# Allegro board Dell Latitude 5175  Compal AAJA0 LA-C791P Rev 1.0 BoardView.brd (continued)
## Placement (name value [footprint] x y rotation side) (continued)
D41  AZ5B25-01F_DFN0603P2Y  [ESD108-B1-CSP0201_WLL-2-1-2]  15.98 22.18 90 bottom
D42  AZ5B25-01F_DFN0603P2Y  [ESD108-B1-CSP0201_WLL-2-1-2]  15.24 22.18 90 bottom
DA2  -  [ESD207-B1-02EL_TSLP-2-19-2]  6.52 143.04 180 top
DA4  -  [PJSOT24CW_SOT323-3]  22.64 127.73 90 top
DA5  -  [ESD207-B1-02EL_TSLP-2-19-2]  12.93 142.76 0 bottom
DA6  -  [ESD207-B1-02EL_TSLP-2-19-2]  11.79 142.63 270 bottom
DA7  -  [PJSOT24CW_SOT323-3]  20.01 100.39 180 bottom
DA8  -  [TVNST52302AB0_SOT523-3]  19.74 83.8 180 bottom
DA9  -  [TVNST52302AB0_SOT523-3]  8.74 141.61 180 top
DA10  -  [ESD207-B1-02EL_TSLP-2-19-2]  5.3 144.76 270 top
DA11  -  [ESD207-B1-02EL_TSLP-2-19-2]  9.9 144 0 top
DI1  -  [TVNST52302AB0_SOT523-3]  179.6 100.12 270 top
DI2  -  [TVNST52302AB0_SOT523-3]  182.97 100.12 90 top
FD1  -  [FIDUCIAL_C40M80]  200.2 151.28 0 top
FD2  -  [FIDUCIAL_C40M80]  6.06 8.54 0 top
FD3  -  [FIDUCIAL_C40M80]  21.85 151.43 180 bottom
FD4  -  [FIDUCIAL_C40M80]  221.02 95.21 180 bottom
H1  -  [H_4P6]  33.78 21.25 0 top
H2  -  [H_4P6]  184.68 90.4 0 top
H3  -  [H_2P3]  9.68 158.92 0 top
H4  -  [H_4P6]  175.58 136.6 0 top
H5  -  [H_4P6]  10.69 115.92 0 top
H6  -  [H_4P6]  69.08 150.9 0 top
H7  -  [H_4P6]  185.68 149.6 0 top
H8  -  [H_1P2]  89.01 114 0 top
H9  -  [H_1P2]  50.83 120 0 top
H10  -  [H_1P5X2P1]  29.64 13.99 0 top
H11  -  [H_2P8]  6.18 3.75 0 top
H13  -  [H_1P4X0P4N]  46.15 100.7 90 top
H14  -  [H_1P4X0P4N]  23.51 125.3 90 top
H15  -  [H_1P4X0P4N]  29.28 131.08 0 top
H16  -  [H_1P4X0P4N]  131.85 109.86 90 top
H17  -  [H_1P4X0P4N]  131.86 122.39 90 top
H18  -  [H_1P4X0P4N]  147.42 104.08 0 top
H19  -  [H_1P3X0P4N]  46.15 124.65 90 top
H20  -  [H_1P4X0P4N]  104.08 128.17 0 top
H21  -  [H_1P4X0P4N]  47.98 93.92 0 top
H22  -  [H_1P4X0P4N]  23.51 113.22 90 top
H23  -  [H_4P6]  21.23 143.17 0 top
H24  -  [H_1P8X1P5]  190.03 148.75 0 top
H25  -  [H_2P8]  9.68 44.74 0 top
H26  -  [H_1P5]  19.48 148.75 0 top
H27  -  [H_1P4X0P4N]  98.3 122.4 90 top
H28  -  [H_1P4X0P4N]  98.3 109.85 90 top
H29  -  [H_1P4X0P4N]  45.11 34.05 90 top
H30  -  [H_1P4X0P4N]  45.11 86 90 top
H31  -  [H_1P4X0P4N]  45.11 61.7 90 top
H32  -  [H_1P4X0P4N]  45.11 69.52 90 top
H33  -  [H_1P4X0P4N]  39.18 89.58 180 top
H34  -  [H_1P4X0P4N]  39.53 67.63 180 top
H35  -  [H_2P8]  9.08 23.85 0 top
JAPS2  ACES_50506-01841-P01  [ACES_50506-01841-P01_18P-NPM]  75.64 129.48 180 top
JCAM3  ACES_50463-0104A-001  [ACES_50463-0104A-001_10P]  101.94 133.18 270 bottom
JDEG1  ACES_50521-01041-P01  [ACES_50521-01041-P01_10P]  192.63 146.6 0 bottom
JDMIC1  E-T_6918K-Y04N-00L  [E-T_6918K-Y04N-00L_4P-T]  152.61 130.94 0 bottom
JEDP1  HRS_FH35C-45S-0P3SHW(50)  [HRS_FH35C-45S-0P3SHW-50_45P-T]  114.03 94.84 180 bottom
JHDMI1  SINGA_2HE2016-100211F  [SINGA_2HE2016-100211F_19P-T]  10.31 49.95 270 top
JHP1  SINGA_2SJ3095-079111F  [SINGA_2SJ3095-079111F_6P-T]  12.56 145.96 270 bottom
JIO1  HRS_DF40C-60DS-0P4V(51)  [HRS_DF40C-60DS-0P4V-51_60P-T]  220.89 120.08 90 bottom
JIO4  HRS_DF40C-100DS-0P4V(51)  [HRS_DF40C-100DS-0P4V-51_100P-T]  140.72 98.34 180 bottom
JLPDE1  ACES_50521-01041-P01  [ACES_50521-01041-P01_10P]  219.73 103.2 270 bottom
JNFC1  LCN_BAM04-20093-0500  [LCN_BAM04-20093-0500_20P]  209.01 98.56 270 bottom
JNGFF1  BELLW_80149-2021  [BELLW_80149-2021_67P]  202.96 148.21 270 bottom
JNGFF2  LCN_DAN05-67216-S503  [LCN_DAN05-67216-S503_75P-T-S]  43.03 104.77 180 bottom
JNGFF3  LCN_DAN05-67216-S500  [LCN_DAN05-67216-S500_75P-T-S]  54.76 133.89 90 bottom
JPWR2  E-T_3806K-F03N-33L  [E-T_3806K-F03N-33L_3P]  41.68 19.4 180 bottom
JRTC1  ACES_50278-00201-001  [ACES_50278-00201-001_2P]  20.18 20.7 180 bottom
JSPI1  ACES_50696-0200M-P01  [ACES_50696-0200M-P01_20P-NPM]  49.71 147.51 180 top
JSPKL  ACES_50208-00201-P03  [ACES_50208-00201-P03_2P]  20.08 80.8 180 bottom
JT100  ACES_50278-01001-001  [ACES_50278-01001-001_10P]  162.29 101.21 180 bottom
JTS1  ACES_50506-01241-P01  [ACES_50506-01241-P01_12P]  176.53 98.48 180 bottom
JUFC  ACES_50515-03941-P02  [ACES_50515-03941-P02_39P]  113.36 134.3 180 bottom
JUSB1  TAIWI_USB034-107CRL-TWD  [TAIWI_USB034-107CRL-TWD_10P-T]  11.78 37.72 90 bottom
JUSBC1  JAE_DX07S024XJ1  [JAE_DX07S024XJ1_24P-T]  8.09 18.8 270 top
JUSH1  E-T_6705K-Y26N-00L  [E-T_6705K-Y26N-00L_26P]  203.43 99.9 180 bottom
JWFC  ACES_50515-03941-P02  [ACES_50515-03941-P02_39P]  133.7 134.3 180 bottom
JXDP1  E-T_6601K-Y61N-04L  [E-T_6601K-Y61N-04L_61P]  75.84 99.12 0 bottom
L1  BLM15PX330SN1D_2P  [MURAT_BLM15PX330SN1D_2P]  8.1 144.12 90 top
L2  BLM15PX330SN1D_2P  [MURAT_BLM15PX330SN1D_2P]  10 140.57 180 top
L3  BLM15AX700SN1D_2P  [MURAT_BLM15AX100SN1D_2P]  7.41 140.93 180 top
L4  DLW21HN900HQ2L_4P  [MURAT_DLW21HN900HQ2L_4P]  53.26 133.8 0 top
L5  FBMA-L11-160808-800LMT_0603  [KC_FBMA-L11-160808-800LMT_2P]  198.03 133.95 180 top
L6  1UH_1269AS-H-1R0M-P2_2.5A_20%  [TOKO_1269AS-H-1R0M-P2_2P]  126.14 130.04 90 top
L7  DLW21HN900HQ2L_4P  [MURAT_DLW21HN900HQ2L_4P]  114.67 127.46 90 top
L8  DLW21HN900HQ2L_4P  [MURAT_DLW21HN900HQ2L_4P]  116.6 127.46 90 top
L9  DLW21HN900HQ2L_4P  [MURAT_DLW21HN900HQ2L_4P]  118.56 127.46 90 top
L10  1NH_LQG15HN1N0S02D_0.3NH  [MURAT_LQG15HN1N0S02D_2P]  72.95 123.41 270 top
L11  BLM18EG221SN1D_2P  [MURAT_BLM18EG221SN1D_2P]  54.76 111.19 90 top
L12  HCM1012GH900BP_4P  [INPAQ_HCM1012GH900BP_4P]  106.98 103.05 270 top
L13  HCM1012GH900BP_4P  [INPAQ_HCM1012GH900BP_4P]  108.38 103.05 270 top
L14  HCM1012GH900BP_4P  [INPAQ_HCM1012GH900BP_4P]  109.77 103.05 270 top
L15  2.2UH_LQM2MPN2R2NG0L_30%  [MURAT_LQM2MPN2R2NG0L_2P]  57.01 101.49 180 top
L16  BLM15AX700SN1D_2P  [MURAT_BLM15AX100SN1D_2P]  8.87 142.79 0 bottom
L17  DLW21HN900HQ2L_4P  [MURAT_DLW21HN900HQ2L_4P]  133.52 124.96 90 bottom
L18  DLW21HN900HQ2L_4P  [MURAT_DLW21HN900HQ2L_4P]  138.83 124.95 90 bottom
L19  DLW21HN900HQ2L_4P  [MURAT_DLW21HN900HQ2L_4P]  144.95 124.95 90 bottom
L20  DLW21HN900HQ2L_4P  [MURAT_DLW21HN900HQ2L_4P]  142.93 124.95 90 bottom
L21  DLW21HN900HQ2L_4P  [MURAT_DLW21HN900HQ2L_4P]  140.77 124.95 90 bottom
L22  DLW21HN900HQ2L_4P  [MURAT_DLW21HN900HQ2L_4P]  209.19 119.4 0 bottom
L23  DLW21HN900HQ2L_4P  [MURAT_DLW21HN900HQ2L_4P]  30.42 111.02 270 bottom
L24  BLM18EG221SN1D_2P  [MURAT_BLM18EG221SN1D_2P]  55.28 122.42 0 top
L25  BLM15HD601SN1D_2P  [MURAT_BLM15HD182SN1D_2P]  150 131.43 90 top
L26  BLM15HD601SN1D_2P  [MURAT_BLM15HD182SN1D_2P]  115.66 131.11 90 top
LA1  0_0603_5%  [R0603_0OHM]  22.12 125.33 90 top
LA2  0_0603_5%  [R0603_0OHM]  40.56 85.78 90 top
LA3  0_0603_5%  [R0603_0OHM]  41.81 85.78 90 top
LA4  0_0603_5%  [R0603_0OHM]  41.64 84.7 0 top
LA5  0_0603_5%  [R0603_0OHM]  25.9 84.65 270 top
LA6  0_0603_5%  [R0603_0OHM]  41.64 83.43 0 top
LA7  0_0603_5%  [R0603_0OHM]  29.36 80.13 90 top
LA8  0_0603_5%  [R0603_0OHM]  41.6 79.19 0 top
LA9  0_0603_5%  [R0603_0OHM]  41.6 77.97 0 top
LA10  BLM21PG600SN1D_2P  [MURAT_BLM21PG600SN1D_2P]  9.56 140.4 0 bottom
LA11  0_0603_5%  [R0603_0OHM]  13.16 137.35 270 bottom
LA12  0_0603_5%  [R0603_0OHM]  16.61 136.03 180 bottom
LA13  BLM15PX181SN1D_2P  [MURAT_BLM15PX181SN1D_2P]  21.26 86.04 270 bottom
LA14  BLM15PX181SN1D_2P  [MURAT_BLM15PX181SN1D_2P]  19.1 86.04 270 bottom
LED1  HT-191UD5_AMBER  [LED_HT-191UD5_2P]  195.94 111.63 270 bottom
LT1  HCB2012KF-121T50_2P  [TAI-T_HCB2012KF-121T50_2P]  18.59 26.8 90 bottom
LX1  DLW21HN900HQ2L_4P  [MURAT_DLW21HN900HQ2L_4P]  19.09 51.03 180 bottom
LX2  DLW21HN900HQ2L_4P  [MURAT_DLW21HN900HQ2L_4P]  18.97 49.27 180 bottom
LX3  DLW21HN900HQ2L_4P  [MURAT_DLW21HN900HQ2L_4P]  19 47.46 180 bottom
LX4  DLW21HN900HQ2L_4P  [MURAT_DLW21HN900HQ2L_4P]  19.02 45.67 180 bottom
MC1  10P_0402_50V8J  [C_0402]  53.21 124.5 0 top
MC2  680P_0402_50V7K  [C_0402]  117.2 110.07 180 top
MD1  -  [TVWDF1004AD0_DFN9]  100.84 127.49 90 top
MD2  AZ1065-06Q.RDG_MSOP8  [AZ1065-06QPRDG_MSOP8]  18.81 36.56 0 bottom
MIC1  WM7211IMSE-RV_LGA5-8  [WM7211IMS-RV_LGA5-8]  11.2 163.26 0 top
MIC2  WM7211IMSE-RV_LGA5-8  [WM7211IMS-RV_LGA5-8]  5.47 116.46 90 top
ML1  CMMI21T-670Y-N_4P  [MURAT_DLW21SN670HQ2L_4P]  203.97 141.82 180 top
ML2  CMMI21T-670Y-N_4P  [MURAT_DLW21SN670HQ2L_4P]  203.95 139.84 180 top
ML3  DLW21HN900HQ2L_4P  [MURAT_DLW21HN900HQ2L_4P]  53.26 132.08 0 top
ML4  CMMI21T-670Y-N_4P  [MURAT_DLW21SN670HQ2L_4P]  96.56 127 0 top
ML5  CMMI21T-670Y-N_4P  [MURAT_DLW21SN670HQ2L_4P]  92.57 126.97 0 top
ML6  DLW21HN900HQ2L_4P  [MURAT_DLW21HN900HQ2L_4P]  29.69 45.66 270 top
ML11  CMMI21T-670Y-N_4P  [MURAT_DLW21SN670HQ2L_4P]  21.25 40.51 270 bottom
ML12  CMMI21T-670Y-N_4P  [MURAT_DLW21SN670HQ2L_4P]  19.48 40.51 270 bottom
ML13  DLW21HN900HQ2L_4P  [MURAT_DLW21HN900HQ2L_4P]  20 28.91 90 bottom
NOREF  -  []  81.56 93.74 0 top
NOREF#2  -  []  33.81 21.25 0 top
NOREF#3  -  []  9.08 23.85 0 top
NOREF#4  -  []  184.68 90.4 0 top
NOREF#5  -  []  175.58 136.6 0 top
NOREF#6  -  []  9.7 158.94 0 top
NOREF#7  -  []  6.18 3.75 0 top
NOREF#8  -  []  9.68 44.74 0 top
NOREF#9  -  []  69.08 150.9 0 top
NOREF#10  -  []  35.31 13.43 0 top
NOREF#11  -  []  89.01 114 0 top
NOREF#12  -  []  50.83 120 0 top
NOREF#13  -  []  29.65 13.89 0 top
NOREF#14  -  []  185.68 149.6 0 top
NOREF#15  -  []  29.63 14.15 0 top
NOREF#16  -  []  98.65 96.21 0 top
NOREF#17  -  []  70.98 54.3 0 top
NOREF#18  -  []  21.23 143.17 0 top
NOREF#19  -  []  10.68 115.95 0 top
NOREF#20  -  []  52.78 96.14 0 top
NOREF#21  -  []  44.28 35.2 180 bottom
NOREF#22  -  []  31.27 65.76 180 bottom
NOREF#23  -  []  35.27 41.82 90 bottom
NOREF#24  -  []  37.36 54.65 180 bottom
NOREF#25  -  []  40.03 26.46 180 bottom
PC100  0.01U_0402_25V7K  [C_0402]  166.32 108.17 0 bottom
PC101  1000P_0402_50V7K  [C_0402]  159.56 105.65 180 bottom
PC105  2200P_0402_50V7K  [C_0402]  166.29 106.06 0 bottom
PC106  2200P_0402_50V7K  [C_0402]  34.71 29.73 90 top
PC107  2200P_0402_50V7K  [C_0402]  33.96 33.59 180 top
PC108  100P_0402_50V8J  [C_0402]  21.31 23.43 270 bottom
PC109  0.01U_0402_25V7K  [C_0402]  20.42 23.43 270 bottom
PC110  1000P_0402_50V7K  [C_0402]  35.27 35.29 0 top
PC111  100P_0402_50V8J  [C_0402]  32.98 37.27 180 top
PC112  0.1U_0402_25V6  [C_0402]  35.27 36.16 0 top
PC113  1U_0603_25V6K  [C_0603]  33.36 35.04 180 top
PC114  0.1U_0402_25V6  [C_0402]  207.99 117.33 180 bottom
PC115  0.1U_0402_25V6  [C_0402]  35.57 29.73 90 top
PC116  0.1U_0402_25V6  [C_0402]  39.07 29.51 90 top
PC117  0.01U_0402_16V7K  [C_0402]  31.29 33.9 0 top
PC118  0.1U_0402_25V6  [C_0402]  31.32 32.15 90 top
PC119  100P_0402_50V8J  [C_0402]  31.22 29.48 180 top
PC120  0.01U_0402_16V7K  [C_0402]  198.22 114.59 90 bottom
PC121  1U_0603_25V6K  [C_0603]  200.88 109.69 0 bottom
PC122  1U_0603_10V7K  [C_0603]  199.4 113.43 180 bottom
PC123  0.1U_0402_25V6  [C_0402]  208.88 114.89 90 bottom
PC124  2200P_0402_50V7K  [C_0402]  42.27 37.68 0 top
PC125  0.1U_0402_25V6  [C_0402]  41.27 40.25 90 top
PC126  2200P_0402_50V7K  [C_0402]  133.35 111.85 270 bottom
PC127  0.1U_0402_25V6  [C_0402]  134.21 111.85 270 bottom
PC150  0.1U_0402_25V6  [C_0402]  184.86 108.42 180 top
PC151  0.1U_0402_25V6  [C_0402]  181.13 108.45 270 top
PC200  0.1U_0402_25V6  [C_0402]  187.17 127.88 0 top
PC400  2.2U_0603_50V6K  [C_0603]  125.44 105.89 90 bottom
PC401  0.1U_0603_50V7K  [C_0603]  122.14 105.61 180 bottom
PC402  0.1U_0603_50V7K  [C_0603]  117.58 106.35 90 bottom
PC403  100P_0402_50V8J  [C_0402]  118.82 107.74 270 bottom
PC404  2.2U_0603_25V6K  [C_0603]  117.53 112.46 180 bottom
PC405  2.2U_0603_50V6K  [C_0603]  122.15 106.81 180 bottom
PC406  2.2U_0603_50V6K  [C_0603]  122.14 108.01 180 bottom
PC407  220P_0402_50V7K  [C_0402]  124.36 111.85 270 bottom
PC408  100P_0402_50V8J  [C_0402]  131.41 103.49 270 top
PC409  100P_0402_50V8J  [C_0402]  127.25 107.27 270 bottom
PC410  1U_0805_50V7K  [C_0805]  124.17 113.58 0 bottom
PC411  100P_0402_50V8J  [C_0402]  127.25 113.16 90 bottom
PC412  0.1U_0402_10V7K  [C_0402]  129.18 113.38 90 bottom
PC413  470P_0402_50V7K  [C_0402]  115.6 101.72 270 top
PC414  470P_0402_50V7K  [C_0402]  116.48 101.69 270 top
PC415  470P_0402_50V7K  [C_0402]  114.71 101.72 270 top
PC416  470P_0402_50V7K  [C_0402]  116.51 102.53 90 top
PC417  470P_0402_50V7K  [C_0402]  113.82 101.77 270 top
PC418  470P_0402_50V7K  [C_0402]  117.4 102.53 90 top
PC500  10U_0805_25V6K  [C_0805]  138.81 120.46 270 bottom
PC501  0.1U_0402_25V6  [C_0402]  142.85 118.73 180 bottom
PC502  2200P_0402_50V7K  [C_0402]  144.02 118.75 0 bottom
PC503  10U_0805_25V6K  [C_0805]  137.07 120.45 270 bottom
PC504  10U_0805_25V6K  [C_0805]  137.11 121.72 90 bottom
PC505  10U_0805_25V6K  [C_0805]  138.94 121.72 90 bottom
PC506  10U_0805_25V6K  [C_0805]  140.66 120.51 270 bottom
PC507  10U_0805_25V6K  [C_0805]  140.7 121.67 90 bottom
PC508  10U_0805_25V6K  [C_0805]  135.3 121.73 90 bottom
PC509  10U_0805_16V6K  [C_0805]  159.96 118.36 90 bottom
PC510  10U_0805_16V6K  [C_0805]  156.39 118.34 90 bottom
PC511  10U_0805_16V6K  [C_0805]  154.54 124.27 90 bottom
PC512  10U_0805_16V6K  [C_0805]  151 116.28 270 bottom
PC513  10U_0805_16V6K  [C_0805]  149.22 124.3 90 bottom
PC514  10U_0805_16V6K  [C_0805]  154.53 116.28 270 bottom
PC515  0.1U_0603_25V7K  [C_0603]  28.21 112.3 0 bottom
PC516  0.1U_0603_25V7K  [C_0603]  26.76 122.48 270 bottom
PC517  0.1U_0603_25V7K  [C_0603]  120.65 117.21 90 bottom
PC518  10U_0805_16V6K  [C_0805]  150.98 124.3 90 bottom
PC519  10U_0805_16V6K  [C_0805]  152.73 124.3 90 bottom
PC520  10U_0805_16V6K  [C_0805]  152.73 116.31 270 bottom
PC521  10U_0805_16V6K  [C_0805]  156.01 122.05 0 bottom
PC522  10U_0805_16V6K  [C_0805]  158.17 118.39 90 bottom
PC523  0.1U_0402_25V6  [C_0402]  144.97 112.93 90 bottom
PC524  0.1U_0402_25V6  [C_0402]  145.91 113.88 270 bottom
PC525  1U_0603_25V6K  [C_0603]  147.31 111.9 180 bottom
PC526  1U_0603_10V6K  [C_0603]  140.36 116.19 90 bottom
PC527  1U_0603_25V6K  [C_0603]  146.43 114.97 180 bottom
PC528  0.1U_0402_25V6  [C_0402]  144.93 110.87 90 bottom
PC529  .047U_0603_50V7  [C_0603]  143.23 117.67 270 bottom
PC530  10U_0805_16V6K  [C_0805]  161.52 114.57 0 bottom
PC531  0.1U_0603_25V7K  [C_0603]  163.25 115.97 90 bottom
PC532  10U_0805_16V6K  [C_0805]  161.51 118.74 0 bottom
PC533  100P_0402_50V8J  [C_0402]  142.32 110.45 180 top
PC534  100P_0402_50V8J  [C_0402]  142.32 109.51 180 top
PC535  0.1U_0402_25V6  [C_0402]  136.23 114.66 0 bottom
PC536  0.1U_0402_25V6  [C_0402]  138.07 114.62 270 bottom
PC537  0.1U_0402_25V6  [C_0402]  137.19 113.76 180 bottom
PC538  1000P_0603_50V7K  [C_0603]  143.51 121.76 180 top
PC539  2200P_0402_50V7K  [C_0402]  159.56 106.77 180 bottom
PC540  1U_0603_25V6K  [C_0603]  137.93 111.87 270 bottom
PC541  2200P_0402_50V7K  [C_0402]  27.66 123.56 0 top
PC542  2200P_0402_50V7K  [C_0402]  142.49 113.73 180 top
PC544  2200P_0402_50V7K  [C_0402]  154.99 112 90 bottom
PC601  0.1U_0402_25V6  [C_0402]  189.35 110 180 bottom
PC602  2200P_0402_50V7K  [C_0402]  189.35 109.11 180 bottom
PC603  0.22U_0402_16V7K  [C_0402]  193.98 115.08 180 bottom
PC604  10U_0603_25V6M  [C_0603]  189.55 106.8 180 bottom
PC605  10U_0603_25V6M  [C_0603]  189.55 108.07 180 bottom
PC606  22U_0603_6.3V6M  [C_0603]  192.06 124.21 0 bottom
PC607  22U_0603_6.3V6M  [C_0603]  192.85 122.9 0 bottom
PC608  22U_0603_6.3V6M  [C_0603]  192.06 125.5 0 bottom
PC609  22U_0603_6.3V6M  [C_0603]  192.85 121.59 0 bottom
PC610  4.7U_0402_6.3V6M  [C_0402]  185.5 112.97 0 bottom
PC611  680P_0603_50V7K  [C_0603]  192.89 119.45 0 bottom
PC612  4.7U_0402_6.3V6M  [C_0402]  193.6 112.11 90 bottom
PC613  0.1U_0402_25V6  [C_0402]  26.06 117.52 90 top
PC614  680P_0603_50V7K  [C_0603]  35.08 114.26 0 bottom
PC615  0.22U_0402_16V7K  [C_0402]  31.22 113.57 90 bottom
PC616  10U_0603_25V6M  [C_0603]  25.02 117.24 90 bottom
PC617  10U_0603_25V6M  [C_0603]  25.02 117.24 90 top
PC618  2200P_0402_50V7K  [C_0402]  26.95 117.52 90 top
PC620  22U_0603_6.3V6M  [C_0603]  41.53 120.31 90 top
PC621  22U_0603_6.3V6M  [C_0603]  40.33 120.33 90 top
PC622  22U_0603_6.3V6M  [C_0603]  41.55 120.49 90 bottom
PC623  22U_0603_6.3V6M  [C_0603]  40.33 120.5 90 bottom
PC624  4.7U_0402_6.3V6M  [C_0402]  29.57 121.36 180 bottom
PC630  1U_0402_16V6K  [C_0402]  192.67 113.02 270 bottom
PC635  1U_0402_16V6K  [C_0402]  29.13 115.33 180 bottom
PC700  10U_0603_25V6M  [C_0603]  125.92 116.09 0 bottom
PC702  0.1U_0402_25V6  [C_0402]  124.43 115.76 270 bottom
PC703  2200P_0402_25V7K  [C_0402]  125.32 115.05 0 bottom
PC704  680P_0402_50V7K  [C_0402]  123.39 125.72 0 top
PC705  0.22U_0402_16V7K  [C_0402]  127.86 124.04 180 bottom
PC710  22U_0603_6.3V6M  [C_0603]  121.03 127.32 180 top
PC711  22U_0603_6.3V6M  [C_0603]  122.14 128.56 0 top
PC712  22U_0603_6.3V6M  [C_0603]  121.03 128.52 180 top
PC713  22U_0603_6.3V6M  [C_0603]  122.14 127.29 0 top
PC714  0.1U_0402_10V7K  [C_0402]  128.28 117.5 0 bottom
PC715  0.22U_0402_10V6K  [C_0402]  122.6 119.74 180 bottom
PC716  10U_0402_6.3V6M  [C_0402]  122.63 118.21 180 bottom
PC717  10U_0402_6.3V6M  [C_0402]  122.57 120.77 180 bottom
PC718  0.1U_0402_10V7K  [C_0402]  127.18 118.18 180 top
PC719  1U_0402_16V6K  [C_0402]  122.61 117.13 180 bottom
PC720  220P_0402_50V8J  [C_0402]  129.17 121.06 180 bottom
PC800  0.047U_0402_25V7K  [C_0402]  32.16 132.25 180 top
PC802  10U_0603_25V6M  [C_0603]  35.94 140.9 90 top
PC803  22U_0603_6.3V6M  [C_0603]  42.14 133.3 0 top
PC804  22U_0603_6.3V6M  [C_0603]  42.14 132.08 0 top
PC805  0.1U_0402_25V6  [C_0402]  37.01 141.39 90 top
PC806  2200P_0402_50V7K  [C_0402]  37.97 141.39 90 top
PC807  470P_0402_50V7K  [C_0402]  35.51 131.59 0 top
PC808  470P_0402_50V7K  [C_0402]  42.32 140.58 0 top
PC809  0.22U_0402_16V7K  [C_0402]  172.87 117.72 180 bottom
PC810  680P_0603_50V7K  [C_0603]  178.71 122.19 0 bottom
PC811  0.1U_0603_25V7K  [C_0603]  177.08 116.08 180 top
PC812  2200P_0402_50V7K  [C_0402]  176.6 113.33 270 bottom
PC813  0.1U_0402_25V6  [C_0402]  177.49 113.33 270 bottom
PC814  10U_0603_25V6M  [C_0603]  179.12 114.56 90 bottom
PC816  47P_0402_50V8J  [C_0402]  170.21 116.63 180 bottom
PC817  22U_0603_6.3V6M  [C_0603]  172.92 124.96 180 bottom
PC818  22U_0603_6.3V6M  [C_0603]  172.93 123.66 180 bottom
PC819  22U_0603_6.3V6M  [C_0603]  172.92 122.37 180 bottom
PC820  22U_0603_6.3V6M  [C_0603]  172.87 126.28 180 bottom
PC821  4.7U_0603_6.3V6K  [C_0603]  172.86 114.71 180 bottom
PC822  4.7U_0603_6.3V6K  [C_0603]  175.52 113.12 180 bottom
PC823  0.1U_0402_25V6  [C_0402]  166.93 114.04 270 bottom
PC901  0.22U_0402_16V7K  [C_0402]  31.81 122.53 0 bottom
PC902  0.1U_0402_25V6  [C_0402]  26.16 126.48 90 bottom
PC903  2200P_0402_50V7K  [C_0402]  27.32 124.49 0 top
PC904  10U_0603_25V6M  [C_0603]  27.09 125.53 0 top
PC905  10U_0603_25V6M  [C_0603]  25.12 126.25 90 bottom
PC906  22U_0603_6.3V6M  [C_0603]  41.11 124.28 270 top
PC907  22U_0603_6.3V6M  [C_0603]  42.39 124.28 270 top
PC908  22U_0603_6.3V6M  [C_0603]  41.11 124.28 270 bottom
PC909  22U_0603_6.3V6M  [C_0603]  42.4 124.28 270 bottom
PC910  4.7U_0402_6.3V6M  [C_0402]  30.17 129.73 180 bottom
PC911  680P_0603_50V7K  [C_0603]  32.05 122.39 0 top
PC912  0.1U_0402_25V6  [C_0402]  28.65 122.24 0 bottom
PC913  0.22U_0402_16V7K  [C_0402]  178.36 103.96 0 top
PC914  10U_0603_25V6M  [C_0603]  177.06 101.01 270 top
PC915  1U_0402_16V6K  [C_0402]  29.75 124.01 180 bottom
PC916  22U_0603_6.3V6M  [C_0603]  173.89 113.37 90 top
PC917  22U_0603_6.3V6M  [C_0603]  171.97 110.18 180 top
PC918  0.1U_0402_25V6  [C_0402]  175.99 101.13 270 top
PC919  2200P_0402_50V7K  [C_0402]  175.08 101.13 270 top
PC920  470P_0402_50V7K  [C_0402]  179.4 110.56 180 top
PC921  470P_0402_50V7K  [C_0402]  171.42 102.13 180 top
PC924  22U_0603_6.3V6M  [C_0603]  172.02 108.88 180 top
PC1000  0.1U_0402_16V7K  [C_0402]  36.11 114.16 180 top
PC1001  22U_0603_6.3V6M  [C_0603]  32.15 112.03 180 top
PC1002  68P_0402_50V8J  [C_0402]  32.6 115.21 270 top
PC1003  22U_0603_6.3V6M  [C_0603]  41.68 110.1 180 top
PC1004  22U_0603_6.3V6M  [C_0603]  43.15 113.65 90 top
PC1005  680P_0402_50V7K  [C_0402]  34.7 109.39 90 top
PC1101  1U_0402_16V6K  [C_0402]  111.01 112.81 0 bottom
PC1102  1U_0402_16V6K  [C_0402]  113.04 124.2 90 bottom
PC1103  330P_0402_50V8J  [C_0402]  118.22 118.86 270 top
PC1104  2200P_0402_25V7K  [C_0402]  108.79 115.22 0 top
PC1105  0.1U_0402_25V6  [C_0402]  108.8 116.11 0 top
PC1106  10U_0805_16V6K  [C_0805]  109.45 116.56 180 bottom
PC1107  10U_0805_16V6K  [C_0805]  109.46 118.28 180 bottom
PC1108  0.22U_0402_10V6K  [C_0402]  108.22 109.81 180 top
PC1109  10U_0805_16V6K  [C_0805]  109.46 120 180 bottom
PC1110  1000P_0603_50V7K  [C_0603]  102.76 113.92 90 top
PC1111  1U_0402_16V6K  [C_0402]  117.36 119.85 0 top
PC1112  1U_0402_16V6K  [C_0402]  117.96 120.26 270 bottom
PC1113  0.022U_0402_16V7K  [C_0402]  117.04 121.15 270 bottom
PC1114  220P_0402_50V8J  [C_0402]  117.7 123.28 0 bottom
PC1115  2200P_0402_25V7K  [C_0402]  116.15 119.37 0 bottom
PC1116  1U_0402_16V6K  [C_0402]  119.61 117.19 90 bottom
PC1117  150P_0402_50V8J  [C_0402]  118.24 116.19 270 top
PC1118  0.01U_0402_16V7K  [C_0402]  118.63 125.05 90 bottom
PC1119  22P_0402_50V8J  [C_0402]  114.73 124.3 180 top
PC1120  22P_0402_50V8J  [C_0402]  114.68 116.27 270 top
PC1121  330P_0402_50V8J  [C_0402]  116.51 122.52 90 top
PC1122  330P_0402_50V8J  [C_0402]  116.43 114.57 270 top
PC1123  0.22U_0402_10V6K  [C_0402]  110.93 122.57 90 bottom
PC1124  0.22U_0402_10V6K  [C_0402]  110.63 116.08 90 bottom
PC1125  1000P_0603_50V7K  [C_0603]  104.01 120.83 0 top
PC1126  1000P_0603_50V7K  [C_0603]  104.03 114.12 0 top
PC1127  0.01U_0402_16V7K  [C_0402]  113.77 125.95 90 bottom
PC1128  0.01U_0402_16V7K  [C_0402]  114.66 125.95 90 bottom
PC1129  0.01U_0402_16V7K  [C_0402]  116.44 113.51 90 bottom
PC1130  0.01U_0402_16V7K  [C_0402]  116.48 116.17 270 bottom
PC1131  2200P_0402_25V7K  [C_0402]  114.92 122.47 180 bottom
PC1132  2200P_0402_25V7K  [C_0402]  114.67 114.79 270 bottom
PC1133  2200P_0402_25V7K  [C_0402]  107.22 121.56 180 top
PC1134  0.1U_0402_25V6  [C_0402]  108.47 115.24 180 bottom
PC1135  10U_0805_16V6K  [C_0805]  106.79 107.24 270 bottom
PC1136  10U_0805_16V6K  [C_0805]  109.47 125.16 180 bottom
PC1137  10U_0805_16V6K  [C_0805]  108.59 107.25 270 bottom
PC1138  150P_0402_50V8J  [C_0402]  113.85 116.53 270 bottom
PC1139  0.1U_0402_25V6  [C_0402]  107.24 120.67 180 top
PC1140  1U_0402_16V6K  [C_0402]  113.02 122.44 90 bottom
PC1141  1U_0402_16V6K  [C_0402]  112.81 116.51 270 bottom
PC1142  2200P_0402_25V7K  [C_0402]  109.32 115.24 0 bottom
PC1143  220P_0402_50V8J  [C_0402]  116.85 122.39 0 bottom
PC1144  150P_0402_50V8J  [C_0402]  113.94 124.2 90 bottom
PC1145  270P_0402_50V7K  [C_0402]  117.55 116.75 270 bottom
PC1146  10U_0805_16V6K  [C_0805]  109.47 123.45 180 bottom
PC1147  10U_0805_16V6K  [C_0805]  109.47 121.73 180 bottom
PC1148  10U_0805_16V6K  [C_0805]  104.99 107.25 270 bottom
PC1149  0.1U_0402_25V6  [C_0402]  115.89 124.2 90 bottom
PC1150  0.1U_0402_25V6  [C_0402]  119.3 115.41 90 bottom
PC1151  47U_D3_20VM_R40M  [C_D3]  107.06 110.9 180 bottom
PC1200  0.1U_0201_6.3V6K  [C_0201]  72.03 111.2 90 top
PC1201  0.1U_0201_6.3V6K  [C_0201]  77.88 112.13 90 top
PC1202  0.1U_0201_6.3V6K  [C_0201]  77.27 111.46 270 top
PC1203  0.1U_0201_6.3V6K  [C_0201]  72.67 111.51 270 top
PC1204  0.1U_0201_6.3V6K  [C_0201]  72.89 115.97 0 top
PC1205  0.1U_0201_6.3V6K  [C_0201]  76.15 111.48 270 top
PC1206  0.1U_0201_6.3V6K  [C_0201]  73.28 111.48 270 top
PC1207  0.1U_0201_6.3V6K  [C_0201]  76.71 111.46 270 top
PC1208  0.1U_0201_6.3V6K  [C_0201]  73.84 111.46 270 top
PC1209  0.1U_0201_6.3V6K  [C_0201]  70.9 120.23 180 top
PC1210  0.1U_0201_6.3V6K  [C_0201]  74.4 116.89 270 top
PC1211  0.1U_0201_6.3V6K  [C_0201]  75.41 115.72 270 top
PC1212  0.1U_0201_6.3V6K  [C_0201]  74.42 114.51 270 top
PC1213  0.1U_0201_6.3V6K  [C_0201]  77.34 114.51 270 top
PC1214  0.1U_0201_6.3V6K  [C_0201]  76.43 119.31 270 top
PC1215  0.1U_0201_6.3V6K  [C_0201]  74.42 113.34 270 top
PC1216  0.1U_0201_6.3V6K  [C_0201]  76.43 114.51 270 top
PC1217  0.1U_0201_6.3V6K  [C_0201]  76.43 116.89 270 top
PC1218  0.1U_0201_6.3V6K  [C_0201]  75.39 119.33 270 top
PC1219  0.1U_0201_6.3V6K  [C_0201]  75.41 116.92 270 top
PC1220  0.1U_0201_6.3V6K  [C_0201]  76.48 113.32 270 top
PC1221  0.1U_0201_6.3V6K  [C_0201]  76.43 115.7 270 top
PC1222  0.1U_0201_6.3V6K  [C_0201]  78.23 114.51 270 top
PC1223  0.1U_0201_6.3V6K  [C_0201]  74.37 118.09 270 top
PC1224  0.1U_0201_6.3V6K  [C_0201]  74.42 115.67 270 top
PC1225  0.1U_0201_6.3V6K  [C_0201]  72.89 113.17 0 top
PC1226  0.1U_0201_6.3V6K  [C_0201]  69.75 118.15 90 top
PC1227  0.1U_0201_6.3V6K  [C_0201]  78.51 112.13 90 top
PC1228  0.1U_0201_6.3V6K  [C_0201]  75.56 111.48 270 top
PC1229  0.1U_0201_6.3V6K  [C_0201]  72.89 115.41 0 top
PC1230  0.1U_0201_6.3V6K  [C_0201]  69.75 119.61 90 top
PC1231  0.1U_0201_6.3V6K  [C_0201]  75.01 111.48 270 top
PC1232  0.1U_0201_6.3V6K  [C_0201]  72.89 114.85 0 top
PC1233  0.1U_0201_6.3V6K  [C_0201]  69.76 117.08 0 top
PC1234  0.1U_0201_6.3V6K  [C_0201]  72.86 116.53 0 top
PC1235  1U_0201_6.3V6M  [C_0201]  74.37 119.31 270 top
PC1236  1U_0201_6.3V6M  [C_0201]  76.43 118.09 270 top
PC1237  0.1U_0201_6.3V6K  [C_0201]  72.83 118.76 0 top
PC1238  0.1U_0201_6.3V6K  [C_0201]  72.86 118.2 0 top
PC1239  0.1U_0201_6.3V6K  [C_0201]  79.15 112.13 90 top
PC1240  0.1U_0201_6.3V6K  [C_0201]  70.92 111.2 90 top
PC1241  0.1U_0201_6.3V6K  [C_0201]  71.48 111.2 90 top
PC1242  0.1U_0201_6.3V6K  [C_0201]  72.86 119.32 0 top
PC1243  0.1U_0201_6.3V6K  [C_0201]  72.86 117.08 0 top
PC1244  0.1U_0201_6.3V6K  [C_0201]  74.42 111.46 270 top
PC1245  1U_0201_6.3V6M  [C_0201]  72.86 117.64 0 top
PC1246  1U_0201_6.3V6M  [C_0201]  69.76 116.53 0 top
PC1247  1U_0201_6.3V6M  [C_0201]  69.84 113.4 180 top
PC1248  1U_0201_6.3V6M  [C_0201]  72.89 114.29 0 top
PC1249  1U_0201_6.3V6M  [C_0201]  72.89 112.61 0 top
PC1250  1U_0201_6.3V6M  [C_0201]  72.89 113.73 0 top
PC1251  1U_0201_6.3V6M  [C_0201]  75.39 118.11 270 top
PC1252  1U_0201_6.3V6M  [C_0201]  79.07 114.51 270 top
PC1253  1U_0201_6.3V6M  [C_0201]  75.41 114.53 270 top
PC1254  1U_0201_6.3V6M  [C_0201]  75.41 113.36 270 top
PC1255  10U_0402_6.3V6M  [C_0402]  81.41 116.02 90 bottom
PC1256  10U_0402_6.3V6M  [C_0402]  81.41 113.76 270 bottom
PC1257  10U_0402_6.3V6M  [C_0402]  83.13 112.23 90 top
PC1258  10U_0402_6.3V6M  [C_0402]  82.45 110.76 90 bottom
PC1259  10U_0402_6.3V6M  [C_0402]  80.57 109.72 270 top
PC1260  10U_0402_6.3V6M  [C_0402]  82.32 109.72 270 top
PC1261  10U_0402_6.3V6M  [C_0402]  81.36 112.21 90 top
PC1262  10U_0402_6.3V6M  [C_0402]  82.24 112.23 90 top
PC1263  10U_0402_6.3V6M  [C_0402]  81.46 109.72 270 top
PC1264  10U_0402_6.3V6M  [C_0402]  83.31 110.76 90 bottom
PC1265  10U_0402_6.3V6M  [C_0402]  83.21 109.72 270 top
PC1266  1U_0201_6.3V6M  [C_0201]  68.59 112.82 0 top
PC1267  1U_0201_6.3V6M  [C_0201]  68.59 115.64 0 top
PC1268  1U_0201_6.3V6M  [C_0201]  68.59 113.96 0 top
PC1269  1U_0201_6.3V6M  [C_0201]  68.59 115.08 0 top
PC1270  1U_0201_6.3V6M  [C_0201]  68.59 114.52 0 top
PC1271  47U_0603_6.3V6M  [C_0603]  98.58 118.21 270 top
PC1272  47U_0603_6.3V6M  [C_0603]  97.36 118.21 270 top
PC1273  47U_0603_6.3V6M  [C_0603]  93.62 117.62 90 bottom
PC1274  47U_0603_6.3V6M  [C_0603]  83.67 115.98 90 bottom
PC1275  47U_0603_6.3V6M  [C_0603]  95.96 123.97 90 top
PC1276  47U_0603_6.3V6M  [C_0603]  94.1 115.62 270 bottom
PC1277  47U_0603_6.3V6M  [C_0603]  82.45 114 270 bottom
PC1278  47U_0603_6.3V6M  [C_0603]  92.4 117.62 90 bottom
PC1279  47U_0603_6.3V6M  [C_0603]  92.89 115.62 270 bottom
PC1280  47U_0603_6.3V6M  [C_0603]  94.72 123.97 90 top
PC1281  47U_0603_6.3V6M  [C_0603]  98.58 114.45 90 top
PC1282  47U_0603_6.3V6M  [C_0603]  97.36 114.45 90 top
PC1283  47U_0603_6.3V6M  [C_0603]  83.77 109.51 270 bottom
PC1284  47U_0603_6.3V6M  [C_0603]  84.43 110.49 90 bottom
PC1285  47U_0603_6.3V6M  [C_0603]  94.08 111.86 90 bottom
PC1286  47U_0603_6.3V6M  [C_0603]  92.86 111.86 90 bottom
PC1287  47U_0603_6.3V6M  [C_0603]  85.63 110.49 90 bottom
PC1288  47U_0603_6.3V6M  [C_0603]  96.14 114.45 90 top
PC1289  47U_0603_6.3V6M  [C_0603]  84.96 109.51 270 bottom
PC1290  47U_0603_6.3V6M  [C_0603]  82.58 109.51 270 bottom
PC1291  47U_0603_6.3V6M  [C_0603]  86.89 104.07 270 top
PC1292  47U_0603_6.3V6M  [C_0603]  90.69 104.08 270 top
PC1293  47U_0603_6.3V6M  [C_0603]  91.92 104.08 270 top
PC1294  47U_0603_6.3V6M  [C_0603]  94.5 104.07 270 top
PC1295  47U_0603_6.3V6M  [C_0603]  84.35 107.36 90 top
PC1296  47U_0603_6.3V6M  [C_0603]  85.62 107.36 90 top
PC1297  47U_0603_6.3V6M  [C_0603]  86.89 107.36 90 top
PC1298  47U_0603_6.3V6M  [C_0603]  99.87 106.83 270 bottom
PC1299  47U_0603_6.3V6M  [C_0603]  93.18 104.07 270 top
PC1300  47U_0603_6.3V6M  [C_0603]  89.46 104.07 270 top
PC1301  47U_0603_6.3V6M  [C_0603]  88.24 104.07 270 top
PC1302  47U_0603_6.3V6M  [C_0603]  82.45 115.99 90 bottom
PC1303  47U_0603_6.3V6M  [C_0603]  96.14 118.21 270 top
PC1304  47U_0603_6.3V6M  [C_0603]  97.18 123.97 90 top
PC1408  0.1U_0402_25V6  [C_0402]  195.91 111.06 90 top
PC1409  0.1U_0402_10V7K  [C_0402]  192.4 114.06 0 top
PC1410  0.1U_0402_10V7K  [C_0402]  186.47 113.22 0 top
PC1411  1U_0603_10V6K  [C_0603]  187.43 119.29 0 top
PC1412  100P_0402_50V8J  [C_0402]  192.48 118.63 0 top
PC1413  0.01UF_0402_25V7K  [C_0402]  192.48 117.48 0 top
PC1414  1U_0603_10V6K  [C_0603]  196.98 114.45 270 top
PC1415  1000P_0402_50V7K  [C_0402]  195.96 115.5 90 top
PC1500  2.2U_0402_6.3V6K  [C_0402]  176.99 118.35 270 top
PC1501  22P_0402_50V8J  [C_0402]  120 117.19 180 top
PD100  -  [TVNST52302AB0_SOT523-3]  156.11 107.04 180 bottom
PD101  -  [TVNST52302AB0_SOT523-3]  151.36 106.87 180 bottom
PD102  -  [SDMK0340L-7-F_SOD323-2]  201.02 107.88 270 bottom
PD103  -  [SDMK0340L-7-F_SOD323-2]  199.31 107.88 270 bottom
PD104  -  [SDMK0340L-7-F_SOD323-2]  197.59 107.88 270 bottom
PD105  -  [SDMK0340L-7-F_SOD323-2]  195.83 107.89 270 bottom
PD400  -  [DFLS160-7_POWERDI123-2]  123.72 107.09 270 bottom
PD401  -  [1N4148WS-7-F_SOD323-2]  118.09 110.99 180 bottom
PD500  -  [SDMK0340L-7-F_SOD323-2]  147.17 110.12 0 top
PD501  -  [SDMK0340L-7-F_SOD323-2]  147.17 113.63 0 top
PD502  -  [SDMK0340L-7-F_SOD323-2]  170.33 103.04 90 bottom
PD503  -  [SDMK0340L-7-F_SOD323-2]  146.68 107.35 90 bottom
PD504  -  [SDMK0340L-7-F_SOD323-2]  147.17 111.88 0 top
PD505  -  [SDMK0340L-7-F_SOD323-2]  135.53 107.25 90 bottom
PD506  -  [SDMK0340L-7-F_SOD323-2]  133.81 107.25 90 bottom
PD1500  -  [BAT54CW_SOT323-3]  179.16 126.28 180 bottom
PH1100  10K_0402_5%_TSM0A103J4302RE  [R_0402]  104.97 104.35 180 top
PH1101  10K_0402_5%_TSM0A103J4302RE  [R_0402]  103.12 126.41 180 bottom
PH1102  10K_0402_5%_TSM0A103J4302RE  [R_0402]  104.3 113.9 180 bottom
PJP602  PAD-OPEN 4x4m  [JUMP_43X118]  188.44 126.2 90 bottom
PJP603  PAD-OPEN 4x4m  [JUMP_43X118]  40.97 117.36 0 bottom
PJP700  -  [JUMP_43X79]  120.39 124.54 180 top
PJP800  -  [JUMP_43X79]  42.68 129.53 0 top
PJP801  -  [JUMP_43X79]  175.83 124.93 90 bottom
PJP900  -  [JUMP_43X79]  41.6 128.03 0 bottom
PJP901  -  [JUMP_43X79]  172.17 112.73 180 top
PJP1000  -  [JUMP_43X79]  43.43 111.22 0 top
PJP1100  PAD-OPEN 4x4m  [JUMP_43X118]  105.96 117.58 0 top
PL101  HCB2012KF-121T50_0805  [TAI-T_HCB2012KF-121T50_2P]  165.02 107.91 270 bottom
PL102  HCB2012KF-121T50_0805  [TAI-T_HCB2012KF-121T50_2P]  162.94 106.11 180 bottom
PL103  HCB2012KF-121T50_0805  [TAI-T_HCB2012KF-121T50_2P]  33.45 30.46 90 top
PL500  HCB2012KF-121T50_0805  [TAI-T_HCB2012KF-121T50_2P]  133.45 119.99 0 bottom
PL501  1.5UH_MMD-06AEI1R5M-M1L_6.5A_20%  [MAG_MMD-06AEI1R5M-M1L_2P]  147.4 120.3 0 bottom
PL600  HCB2012KF-121T50_0805  [TAI-T_HCB2012KF-121T50_2P]  193.13 106.92 180 bottom
PL601  1.5UH_MMD-06AEI1R5M-M1L_6.5A_20%  [MAG_MMD-06AEI1R5M-M1L_2P]  188.47 116.5 90 bottom
PL602  HCB2012KF-121T50_0805  [TAI-T_HCB2012KF-121T50_2P]  26.91 111.74 90 bottom
PL603  1.5UH_MMD-06AEI1R5M-M1L_6.5A_20%  [MAG_MMD-06AEI1R5M-M1L_2P]  31.68 118.45 0 bottom
PL605  HCB2012KF-121T50_0805  [TAI-T_HCB2012KF-121T50_2P]  25.25 111.74 90 bottom
PL700  HCB2012KF-121T50_0805  [TAI-T_HCB2012KF-121T50_2P]  121.31 115.86 0 bottom
PL701  1UH_PCME051E-1R0MS_6.5A_20%  [CYNTE_PCME051E-1R0MS_2P]  124.83 124.49 180 bottom
PL802  1UH_PCMB041B-1R0MS_4.2A_20%  [CYNTE_PCMB041B-1R0MS_2P]  39.22 134.84 270 top
PL803  HCB2012KF-121T50_0805  [TAI-T_HCB2012KF-121T50_2P]  179.17 111.05 90 bottom
PL804  1UH_PCMB041B-1R0MS_4.2A_20%  [CYNTE_PCMB041B-1R0MS_2P]  175.83 118.96 90 bottom
PL805  HCB2012KF-121T50_0805  [TAI-T_HCB2012KF-121T50_2P]  35.99 137.67 90 top
PL806  HCB2012KF-121T50_0805  [TAI-T_HCB2012KF-121T50_2P]  34.34 137.67 90 top
PL900  HCB2012KF-121T50_0805  [TAI-T_HCB2012KF-121T50_2P]  25.33 123.04 90 bottom
PL901  1.5UH_MMD-06AEI1R5M-M1L_6.5A_20%  [MAG_MMD-06AEI1R5M-M1L_2P]  32.51 126.58 0 bottom
PL903  HCB1608KF-121T30_0603  [TAI-T_HCB1608KF-121T3_L0603_2P]  180.06 102.02 180 top
PL904  1UH_PCMB041B-1R0MS_4.2A_20%  [CYNTE_PCMB041B-1R0MS_2P]  175.67 107.46 90 top
PL1000  HCB1608KF-121T30_0603  [TAI-T_HCB1608KF-121T3_L0603_2P]  33.48 110.56 180 top
PL1001  1UH_PCMB041B-1R0MS_4.2A_20%  [CYNTE_PCMB041B-1R0MS_2P]  37.59 113.16 0 top
PL1102  0.47UH_FDSD0412-H-R47M-P3_5.6A_20%  [TOKO_FDSD0412-H-R47M-P3_2P]  103.62 109.88 270 top
PL1103  0.15UH_MMD-05AE-R15MEM1L_16A_20%  [MAG_MMD-05AE-R15MEM1L_2P]  101 123.01 0 bottom
PL1104  0.15UH_MMD-05AE-R15MEM1L_16A_20%  [MAG_MMD-05AE-R15MEM1L_2P]  105.33 117.4 180 bottom
PL1105  4.7UH_1239AS-H-4R7M-P2_1.3A_20%  [TOKO_1239AS-H-4R7M-P2_2P]  120.04 109.84 0 bottom
PQ104  -  [AON7405_DFN8-5]  43.29 30.06 90 top
PQ105  -  [DMN65D8LW-7_SOT323-3]  37.38 32.34 270 top
PQ106  -  [DMN66D0LDW-7_SOT363-6]  27.24 84.24 0 top
PQ107  -  [DMP3099L-7_SOT23-3]  203.25 115.48 270 bottom
PQ108  -  [DMP3099L-7_SOT23-3]  196.3 118.15 90 bottom
PQ109  -  [DMN66D0LDW-7_SOT363-6]  202.4 119.31 270 bottom
PQ112  -  [DMN65D8LW-7_SOT323-3]  206.96 113.42 0 bottom
PQ150  -  [DMN66D0LDW-7_SOT363-6]  183.59 103.52 0 top
PQ151  -  [DMN65D8LW-7_SOT323-3]  183.35 114.82 90 top
PQ202  -  [DMN65D8LW-7_SOT323-3]  190.37 128.07 0 top
PQ300  -  [DMN65D8LW-7_SOT323-3]  145.77 121.15 0 top
PQ400  -  [P5103EMG_SOT23-3]  119.28 113.02 90 bottom
PQ500  -  [AON7407_DFN8-5]  160.43 108.27 90 bottom
PQ501  AON7934_DFN3X3A-8-10  [AON7934_DFN3X3A8-10]  144.59 119.92 180 bottom
PQ502  -  [AON7407_DFN8-5]  158.95 110.28 270 bottom
PQ503  -  [AON7405_DFN8-5]  159.22 114.26 270 bottom
PQ504  -  [DMN65D8LW-7_SOT323-3]  165.95 112.56 180 bottom
PQ505  -  [DMN65D8LW-7_SOT323-3]  169.54 110.76 0 bottom
PQ506  -  [DMN65D8LW-7_SOT323-3]  169.54 109.44 180 bottom
PQ509  -  [AON7407_DFN8-5]  152.07 108.32 90 bottom
PQ510  -  [AON7407_DFN8-5]  150.8 110.43 270 bottom
PQ511  -  [DMN65D8LW-7_SOT323-3]  150.94 112.61 90 bottom
PQ512  -  [DMN65D8LW-7_SOT323-3]  143.98 106.44 90 bottom
PQ513  -  [DMN65D8LW-7_SOT323-3]  140.34 106.29 90 bottom
PQ800  -  [DMN65D8LW-7_SOT323-3]  168.16 115.78 90 bottom
PQ1100  -  [AON7934_DFN3X3A8-10]  109.31 114.05 180 top
PQ1500  -  [DMN65D8LW-7_SOT323-3]  180.11 115.45 270 top
PQ1501  -  [DMN66D0LDW-7_SOT363-6]  185.01 116.67 0 top
PQ1502  -  [DMN66D0LDW-7_SOT363-6]  187.41 118.02 270 top
PR106  100_0402_1%  [R_0402]  157.63 106.57 270 bottom
PR108  100_0402_1%  [R_0402]  154.66 106.54 270 bottom
PR109  0_0402_5%  [R0402_0OHM]  152.81 105.63 90 bottom
PR116  200K_0402_1%  [R_0402]  38.18 29.5 90 top
PR117  200K_0402_1%  [R_0402]  34.34 35.91 270 top
PR118  36.5K_0402_1%  [R_0402]  36.14 34.39 180 top
PR121  169K_0402_1%  [R_0402]  32.21 30.37 180 top
PR122  200K_0402_1%  [R_0402]  39.06 31.32 180 top
PR125  100K_0402_1%  [R_0402]  32.21 31.26 180 top
PR126  100K_0402_1%  [R_0402]  32.18 32.12 90 top
PR127  30K_0402_1%  [R_0402]  28.52 30.04 0 top
PR128  1M_0402_1%  [R_0402]  199.11 114.59 90 bottom
PR129  10K_0402_1%  [R_0402]  204.29 118.02 180 bottom
PR130  0_0402_5%  [R0402_0OHM]  207.99 116.44 180 bottom
PR131  100K_0402_1%  [R_0402]  196.04 120.56 0 bottom
PR132  300K_0402_5%  [R_0402]  203.2 109.51 90 bottom
PR133  0_0402_5%  [R0402_0OHM]  198.73 120.56 180 bottom
PR134  300K_0402_5%  [R_0402]  209.74 114.89 90 bottom
PR135  20K_0402_1%  [R_0402]  24.99 30.04 0 top
PR136  0_0805_5%  [R_0805]  200.8 112.68 0 bottom
PR137  100K_0402_1%  [R_0402]  28.03 87.19 180 top
PR138  1M_0402_1%  [R_0402]  27.66 30.04 180 top
PR151  100K_0402_5%  [R_0402]  182.91 107.39 180 top
PR152  100K_0402_5%  [R_0402]  182.08 115.27 270 top
PR153  100K_0402_5%  [R_0402]  180.26 110.4 270 top
PR154  10K_0402_1%  [R_0402]  183.97 107.43 0 top
PR155  10K_0402_1%  [R_0402]  182.91 108.41 180 top
PR156  10K_0402_1%  [R_0402]  180.29 113.68 270 top
PR157  10K_0402_1%  [R_0402]  181.2 114.35 90 top
PR158  100K_0402_5%  [R_0402]  181.51 105.48 0 top
PR300  220K_0402_1%  [R_0402]  147.52 121.69 270 top
PR301  220K_0402_1%  [R_0402]  151.03 119.99 90 top
PR302  390K_0402_1%  [R_0402]  145.14 118.04 0 top
PR303  20_0402_1%  [R_0402]  147.52 119.94 270 top
PR400  100K_0402_5%  [R_0402]  119.82 108.11 270 bottom
PR401  10_0603_5%  [R_0603]  123.24 110.81 90 bottom
PR402  0_0402_5%  [R0402_0OHM]  119.83 106.34 270 bottom
PR403  10K_0402_1%  [R_0402]  129.64 102.58 90 top
PR404  51_0402_5%  [R_0402]  123.09 113.63 90 bottom
PR405  1M_0402_1%  [R_0402]  130.52 103.5 270 top
PR406  10K_0402_1%  [R_0402]  129.2 106.27 90 bottom
PR407  1M_0402_1%  [R_0402]  128.31 107.19 270 bottom
PR408  62K_0402_1%  [R_0402]  128.3 113.38 90 bottom
PR409  10K_0402_1%  [R_0402]  120.17 116.32 270 bottom
PR500  0.01_1206_1%  [R_1206_4P-D]  134.16 113.39 90 bottom
PR501  0_0402_5%  [R0402_0OHM]  147.73 112.97 180 bottom
PR502  0_0402_5%  [R0402_0OHM]  147.7 113.91 180 bottom
PR503  0_0402_5%  [R0402_0OHM]  143.59 111.39 90 top
PR504  10_1206_5%  [R_1206]  145.05 113.63 90 top
PR505  294K_0402_1%  [R_0402]  144.37 108.5 0 bottom
PR506  100K_0402_1%  [R_0402]  144.37 109.36 0 bottom
PR507  2.2_0603_5%  [R_0603]  141.63 116.26 90 bottom
PR508  0_0402_5%  [R0402_0OHM]  141.02 108.47 90 bottom
PR509  100K_0402_1%  [R_0402]  145.55 110.66 90 top
PR510  0_0402_5%  [R0402_0OHM]  140.11 108.47 90 bottom
PR511  0.01_1206_1%  [R_1206_4P-D]  157.05 116.6 0 bottom
PR512  0_0402_5%  [R0402_0OHM]  145.55 112.49 180 top
PR513  0_0402_5%  [R0402_0OHM]  145.07 109.29 180 top
PR514  4.7_1206_5%  [R_1206]  143.51 117.69 90 top
PR515  1M_0402_1%  [R_0402]  160.58 113.2 270 bottom
PR516  154K_0402_1%  [R_0402]  144.67 111.57 270 top
PR517  0_0402_5%  [R0402_0OHM]  145.07 108.41 180 top
PR518  604K_0402_1%  [R_0402]  163.35 112.25 90 bottom
PR519  390K_0402_1%  [R_0402]  161.51 112.28 0 bottom
PR520  1K_0402_1%  [R_0402]  161.51 113.19 0 bottom
PR521  0_0402_5%  [R0402_0OHM]  141.96 108.47 90 bottom
PR522  0_0402_5%  [R0402_0OHM]  145.07 107.53 180 top
PR523  10K_0402_1%  [R_0402]  138.12 115.59 90 bottom
PR524  1K_0402_1%  [R_0402]  164.22 112.25 90 bottom
PR525  20K_0402_1%  [R_0402]  142.32 108.6 180 top
PR526  4.02K_0402_1%  [R_0402]  138.1 112.82 180 bottom
PR527  390K_0402_1%  [R_0402]  167.79 111.29 90 bottom
PR528  2.2K_0402_5%  [R_0402]  167.64 110.4 0 bottom
PR529  300K_0402_1%  [R_0402]  137.31 108.47 90 bottom
PR530  10_0603_1%  [R_0603]  141.11 112.59 0 top
PR531  0_0402_5%  [R0402_0OHM]  139.19 108.47 90 bottom
PR532  115K_0402_1%  [R_0402]  138.25 109.36 270 bottom
PR533  0_0402_5%  [R0402_0OHM]  141.38 111.47 0 top
PR534  75K_0402_1%  [R_0402]  153.14 112 90 bottom
PR535  0_0402_5%  [R0402_0OHM]  128.32 105.42 0 bottom
PR536  300K_0402_5%  [R_0402]  164.22 114.05 0 bottom
PR537  1K_0402_1%  [R_0402]  154.05 111.98 90 bottom
PR538  1K_0402_1%  [R_0402]  152.22 112.92 270 bottom
PR539  180K_0402_1%  [R_0402]  148.03 107.23 0 bottom
PR540  0_0402_5%  [R0402_0OHM]  149.89 106.42 270 bottom
PR541  1M_0402_1%  [R_0402]  145.06 107.61 270 bottom
PR542  1M_0402_1%  [R_0402]  143.51 109.08 270 bottom
PR543  1M_0402_1%  [R_0402]  136.85 105.63 90 bottom
PR544  604K_0402_1%  [R_0402]  148.65 114.33 0 bottom
PR545  1M_0402_1%  [R_0402]  145.05 105.79 0 bottom
PR546  200K_0402_1%  [R_0402]  135.05 110.99 0 bottom
PR547  20K_0402_1%  [R_0402]  148.95 106.34 180 bottom
PR548  20K_0402_1%  [R_0402]  148.95 105.45 180 bottom
PR549  220K_0402_1%  [R_0402]  147.29 106.34 90 top
PR550  36.5K_0402_1%  [R_0402]  136.85 110.96 90 bottom
PR557  340K_0402_1%  [R_0402]  171.3 107.3 90 bottom
PR558  1M_0402_1%  [R_0402]  171.53 109.46 90 bottom
PR603  3.3_0603_1%  [R_0603]  192.53 114.04 0 bottom
PR604  4.7_0805_5%  [R_0805]  193.29 116.37 90 bottom
PR605  100K_0402_5%  [R_0402]  186.4 111.57 180 bottom
PR606  0_0402_5%  [R0402_0OHM]  193.58 110.37 180 bottom
PR607  22K_0402_1%  [R_0402]  29.08 113.32 90 bottom
PR608  0_0402_5%  [R0402_0OHM]  193.57 111.26 180 bottom
PR609  4.7_0805_5%  [R_0805]  32.23 114.04 0 bottom
PR610  0_0402_5%  [R_0402]  28.19 113.32 90 bottom
PR611  1M_0402_5%  [R_0402]  194.51 111.27 90 bottom
PR612  22K_0402_1%  [R_0402]  27.33 115.23 180 bottom
PR617  3.3_0603_1%  [R_0603]  30.15 114.82 270 bottom
PR618  100K_0402_5%  [R_0402]  25.74 121.04 180 bottom
PR701  75_0402_5%  [R_0402]  129.18 121.94 180 bottom
PR703  4.7_0805_5%  [R_0805]  123.89 122.99 90 top
PR704  100K_0402_1%  [R_0402]  129.23 120.17 180 bottom
PR705  0_0402_5%  [R0402_0OHM]  129.19 115.72 180 bottom
PR706  100K_0402_1%  [R_0402]  128.31 119.29 0 bottom
PR707  1M_0402_1%  [R_0402]  128.27 116.61 0 bottom
PR708  0_0402_5%  [R0402_0OHM]  126.26 117.29 0 top
PR709  0_0402_5%  [R_0402]  128.99 117.29 180 top
PR710  1M_0402_1%  [R_0402]  128.07 118.18 0 top
PR711  2.2_0603_5%  [R_0603]  127.01 122.99 0 bottom
PR712  100K_0402_5%  [R_0402]  123.13 118.79 270 top
PR718  150K_0402_1%  [R_0402]  128.31 118.39 0 bottom
PR722  0_0402_5%  [R0402_0OHM]  122.15 117.89 90 top
PR800  100K_0402_1%  [R_0402]  33.93 130.39 90 top
PR801  0_0402_5%  [R0402_0OHM]  32.99 132.25 0 top
PR802  100K_0402_1%  [R_0402]  33.01 131.31 270 top
PR803  1K_0402_1%  [R_0402]  31.24 130.42 0 top
PR804  1M_0402_5%  [R_0402]  32.13 131.33 180 top
PR805  4.7_0805_5%  [R_0805]  35.98 134.31 270 top
PR806  499K_0402_1%  [R_0402]  42.32 135.27 0 top
PR807  0_0402_5%  [R_0402]  41.95 142.36 270 top
PR808  0_0402_5%  [R0402_0OHM]  42.32 136.16 0 top
PR809  200K_0402_1%  [R_0402]  42.32 139.69 0 top
PR810  0_0402_5%  [R0402_0OHM]  42.32 137.05 0 top
PR811  0_0402_5%  [R0402_0OHM]  42.32 138.8 0 top
PR812  0_0402_5%  [R0402_0OHM]  42.32 137.91 0 top
PR813  150K_0402_1%  [R_0402]  171.02 118.61 90 bottom
PR815  4.7_1206_5%  [R_1206]  179.22 118.2 90 bottom
PR816  0_0603_5%  [R_0603]  175.67 114.87 0 top
PR817  36.5K_0402_1%  [R_0402]  171.07 116.65 270 bottom
PR818  10K_0402_5%  [R_0402]  171.94 120.43 0 bottom
PR819  0_0402_5%  [R_0402]  171.94 119.55 0 bottom
PR820  62K_0402_1%  [R_0402]  172.85 115.74 90 bottom
PR821  0_0402_5%  [R0402_0OHM]  172.85 118.61 180 bottom
PR822  0_0402_5%  [R_0402]  40.64 142.31 180 top
PR823  402K_0402_1%  [R_0402]  170.2 115.75 180 bottom
PR824  100K_0402_5%  [R_0402]  170.21 113.96 180 bottom
PR825  100K_0402_1%  [R_0402]  38.86 142.31 270 top
PR826  100K_0402_1%  [R_0402]  39.73 141.42 0 top
PR827  100K_0402_1%  [R_0402]  43.71 142.36 270 top
PR828  100K_0402_1%  [R_0402]  42.82 141.44 90 top
PR829  0_0402_5%  [R_0402]  170.2 114.86 180 bottom
PR830  1M_0402_1%  [R_0402]  167.83 114.05 270 bottom
PR831  0_0402_5%  [R_0402]  171.96 116.65 270 bottom
PR903  3.3_0603_1%  [R_0603]  30.78 123.63 270 bottom
PR904  4.7_0805_5%  [R_0805]  32.49 125.26 270 top
PR905  100K_0402_5%  [R_0402]  26.21 129.61 270 bottom
PR906  22K_0402_1%  [R_0402]  27.8 121.93 270 bottom
PR907  100K_0402_1%  [R_0402]  179.34 106.74 180 top
PR908  0_0402_5%  [R_0402]  179.34 104.88 180 top
PR909  100K_0402_1%  [R_0402]  178.43 105.82 0 top
PR910  150K_0402_1%  [R_0402]  179.27 103.06 180 top
PR911  0_0402_5%  [R0402_0OHM]  27.79 123.09 90 bottom
PR912  4.7_0805_5%  [R_0805]  178.9 107.74 90 top
PR913  499K_0402_1%  [R_0402]  171.45 106.59 180 top
PR914  0_0402_5%  [R0402_0OHM]  171.43 100.2 90 top
PR915  22K_0402_1%  [R_0402]  29.77 123.12 180 bottom
PR916  499K_0402_1%  [R_0402]  171.45 103.07 180 top
PR917  0_0402_5%  [R0402_0OHM]  171.45 104.82 180 top
PR918  0_0402_5%  [R0402_0OHM]  171.45 103.96 180 top
PR920  0_0402_5%  [R0402_0OHM]  173.25 100.2 90 top
PR921  1M_0402_1%  [R_0402]  174.16 101.11 270 top
PR922  1M_0402_1%  [R_0402]  172.35 101.11 270 top
PR1000  0_0402_5%  [R0402_0OHM]  36.11 115.05 180 top
PR1001  100K_0402_5%  [R_0402]  30.81 114.01 0 top
PR1003  4.7_0603_5%  [R_0603]  35.79 110.63 270 top
PR1004  20K_0402_1%  [R_0402]  33.49 115.21 270 top
PR1005  10K_0402_1%  [R_0402]  34.35 114.29 90 top
PR1006  0_0402_5%  [R0402_0OHM]  120.18 116.27 180 top
PR1100  2.32K_0402_1%  [R_0402]  120 118.07 180 top
PR1102  2K_0402_1%  [R_0402]  120 118.96 180 top
PR1103  0_0603_5%  [R_0603]  109.45 108.37 90 top
PR1105  1.91K_0402_1%  [R_0402]  116.64 124.32 180 top
PR1106  100_0402_1%  [R_0402]  116.41 118.58 180 top
PR1107  0_0402_5%  [R0402_0OHM]  119.52 121.76 180 bottom
PR1108  10K_0402_1%  [R_0402]  116.41 119.47 180 top
PR1109  4.7_0805_5%  [R_0805]  104.44 112.4 180 top
PR1111  45.3_0402_1%  [R_0402]  116.41 120.36 180 top
PR1112  1K_0402_1%  [R_0402]  109.41 106.56 90 top
PR1113  10_0402_5%  [R_0402]  114.66 118.52 180 top
PR1114  10K_0402_1%  [R_0402]  115.37 117.19 0 top
PR1115  0_0402_5%  [R0402_0OHM]  114.66 119.47 180 top
PR1116  2.61K_0402_1%  [R_0402]  120.09 120.84 270 bottom
PR1117  49.9_0402_1%  [R_0402]  114.66 120.36 180 top
PR1118  5.76K_0402_1%  [R_0402]  117.72 124.17 0 bottom
PR1119  11K_0402_1%  [R_0402]  116.15 121.15 270 bottom
PR1120  10K_0402_1%  [R_0402]  116.15 117.59 90 bottom
PR1121  75_0402_5%  [R_0402]  117.34 117.95 90 top
PR1122  34K_0402_1%  [R_0402]  118.72 117.19 90 bottom
PR1123  127K_0402_1%  [R_0402]  117.35 116.19 270 top
PR1124  1.69K_0402_1%  [R_0402]  117.04 117.59 90 bottom
PR1126  0_0402_5%  [R_0402]  113.87 123.43 270 top
PR1127  0_0402_5%  [R_0402]  114.66 114.5 0 top
PR1129  2K_0402_1%  [R_0402]  115.65 123.43 270 top
PR1130  2.67K_0402_1%  [R_0402]  114.76 123.43 270 top
PR1131  2.8K_0402_1%  [R_0402]  115.56 116.29 270 top
PR1132  2K_0402_1%  [R_0402]  116.43 116.3 270 top
PR1134  0_0603_5%  [R_0603]  111.98 123.97 270 bottom
PR1135  0_0603_5%  [R_0603]  111.75 116.41 270 bottom
PR1137  4.7_0805_5%  [R_0805]  105.03 122.01 90 top
PR1138  4.7_0805_5%  [R_0805]  103.78 118.11 270 top
PR1141  4.87K_0402_1%  [R_0402]  110.68 126.74 180 bottom
PR1142  4.87K_0402_1%  [R_0402]  113.79 113.23 180 bottom
PR1143  11K_0402_1%  [R_0402]  112.85 125.95 90 bottom
PR1144  11K_0402_1%  [R_0402]  115.57 113.48 90 bottom
PR1145  1.27K_0402_1%  [R_0402]  114.92 123.33 180 bottom
PR1146  1.27K_0402_1%  [R_0402]  115.62 116.16 270 bottom
PR1147  10K_0402_1%  [R_0402]  115.85 123.33 270 bottom
PR1148  10K_0402_1%  [R_0402]  114.73 116.53 270 bottom
PR1149  3.24K_0402_1%  [R_0402]  116.84 123.26 90 bottom
PR1150  3.24K_0402_1%  [R_0402]  118.41 116.32 270 bottom
PR1151  100K_0402_1%  [R_0402]  114.83 124.2 90 bottom
PR1152  100K_0402_1%  [R_0402]  113.7 114.76 180 bottom
PR1153  3.65K_0603_1%  [R_0603]  112.94 112.18 0 bottom
PR1154  3.65K_0603_1%  [R_0603]  119.03 119.45 90 bottom
PR1155  3.65K_0603_1%  [R_0603]  111.75 125.29 90 bottom
PR1413  10K_0402_1%  [R_0402]  191.35 118.67 180 top
PR1414  84.5K_0402_1%  [R_0402]  195.02 115.5 90 top
PR1416  2M_0402_5%  [R_0402]  195.01 111.08 90 top
PR1417  2M_0402_5%  [R_0402]  194.08 115.5 90 top
PR1418  232K_0402_1%  [R_0402]  196.88 115.59 90 top
PR1419  232K_0402_1%  [R_0402]  197.74 111.98 270 top
PR1420  22.6K_0402_1%  [R_0402]  193.17 116.41 270 top
PR1421  10K_0402_1%  [R_0402]  191.35 117.5 180 top
PR1422  42.2K_0402_1%  [R_0402]  195.88 113.05 90 top
PR1423  48.7K_0402_1%  [R_0402]  194.97 113.96 270 top
PR1424  10K_0402_1%  [R_0402]  189.47 113.27 180 top
PR1425  84.5K_0402_1%  [R_0402]  196.82 111.06 90 top
PR1500  100K_0402_5%  [R_0402]  178.47 112.77 90 top
PR1501  100K_0402_5%  [R_0402]  183.31 119.09 180 top
PR1502  100K_0402_5%  [R_0402]  183.31 118.15 180 top
PR1503  820K_0402_1%  [R_0402]  183.31 117.24 180 top
PR1504  100K_0402_5%  [R_0402]  179.41 113.68 270 top
PR1510  1M_0402_1%  [R_0402]  169.02 103.06 90 bottom
PR1556  0_0603_5%  [R_0603]  109.52 119.41 90 top
PR1557  0_0603_5%  [R_0603]  109.54 123.38 270 top
PR1558  0_0603_5%  [R_0603]  109.54 117.03 90 top
PTC800  PAD~D  [TPC12]  41.3 141.19 0 top
PTC801  PAD~D  [TPC12]  41.3 142.53 0 top
PU100  -  [LM393DMR2G_MICRO8]  25.9 33.73 270 top
PU101  -  [RT9069-33GB_SOT23-5]  199.47 109.74 180 bottom
PU150  -  [SN74LVC1G123DCUR_VSSOP8]  185.46 112.64 180 top
PU151  -  [SN74LVC1G123DCUR_VSSOP8]  182.91 112.9 180 top
PU200  -  [SN74AUP1T08DCKR_SC70-5]  185.87 126.55 270 top
PU300  -  [74LVC1G32GW_TSSOP5]  149.85 121.17 180 top
PU400  -  [TPS61181ARTER_QFN16_3X3]  125.65 109.44 90 bottom
PU500  -  [BQ24770RUYR_WQFN28_4X4]  143.6 113.94 180 bottom
PU600  -  [NB680GD-Z_QFN12_2X3]  189.76 111.72 90 bottom
PU601  -  [NB679GD-Z_QFN12_2X3]  27.02 117.7 0 bottom
PU700  -  [NB685GQ-Z_QFN16_3X3]  125.95 118.26 90 bottom
PU801  -  [SYX196DQNC_QFN10_3X3]  174.43 117.03 270 bottom
PU808  -  [SY8057QDC_QFN16_3X3]  38.73 136.67 90 top
PU900  -  [NB680GD-Z_QFN12_2X3]  27.9 126.39 0 bottom
PU901  -  [SY8057QDC_QFN16_3X3]  175.34 105.53 270 top
PU1000  -  [SY8003DFC_DFN8_2X2]  33.42 113.11 270 top
PU1100  -  [ISL95808HRZ-TS2378_DFN8_2X2]  106.72 106.07 0 top
PU1101  -  [ISL95852HIZ-T_WLCSP64]  111.33 121.2 270 bottom
PU1403  -  [M74VHC1GT00DFT2G_SC70-5]  191.4 114.33 90 top
PU1404  -  [M74VHC1GT00DFT2G_SC70-5]  188.56 114.29 90 top
PU1500  -  [SN74LVC1G123DCUR_VSSOP8]  181.12 117.35 90 top
PU1501  -  [LM393DMR2G_MICRO8]  187.01 112.01 270 top
Q1  DII-DMN65D8LW-7  [SSM3K7002FU_SC70-3]  205.09 143.14 270 top
Q3  -  [MMBT3904WH_SOT323-3]  214.78 138 0 top
Q4  -  [DMN66D0LDW-7_SOT363-6]  209.51 134.62 270 top
Q5  -  [DMN66D0LDW-7_SOT363-6]  206.13 131.42 0 top
Q6  DII-DMN65D8LW-7  [SSM3K7002FU_SC70-3]  191.12 131.31 90 top
Q7  -  [DMN2400UV-7_SOT-563-6]  51.78 129.61 90 top
Q8  -  [DMN2400UV-7_SOT-563-6]  139.96 129.24 0 top
Q9  -  [LP2301ALT1G_SOT23-3]  146.19 127.36 270 top
Q11  -  [MMBT3904WH_SOT323-3]  84.62 120.9 90 top
Q12  -  [MMBT3904WH_SOT323-3]  141.92 119.85 270 top
Q14  -  [MMBT3904WH_SOT323-3]  78.43 133.81 180 bottom
Q15  DII-DMN65D8LW-7  [SSM3K7002FU_SC70-3]  205.32 118.99 90 bottom
Q16  DII-DMN65D8LW-7  [SSM3K7002FU_SC70-3]  195.72 113.37 180 bottom
Q17  -  [DMN2400UV-7_SOT-563-6]  35.47 112.68 270 bottom
